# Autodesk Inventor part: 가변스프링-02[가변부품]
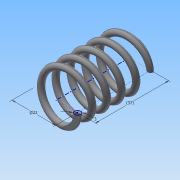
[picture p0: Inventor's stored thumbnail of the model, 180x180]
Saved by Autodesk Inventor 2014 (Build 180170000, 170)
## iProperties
Created: 2015-09
Part Number: 가변스프링-02[가변부품]
Material: 강철, 탄소
Document SubType Name: Modeling
Designer: study
Density: 7.87 g/cm^3
Appearance: 반연마
Mass: 18.8856 g
Surface Area: 32.5491 cm^2
Volume: 2.3997 cm^3
Author: study
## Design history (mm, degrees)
sketch "스케치1"
  geometry: L1 (0, 0)-(11, 0); L2 (11, 0)-(11, 36.411); L3 (11, 36.411)-(0, 36.411); L4 (0, 36.411)-(0, 0); C1 r 1.5 at (11, 0)
  constraints: 8 end point, 2 parallel, 1 centre point, 1 coincident, 1 horizontal, 1 perpendicular
  dimensions: "d0" = 22 diameter of L2 L4; "d1" = 36.4112 distance of L1.end L2.end (derived); "d2" = 3 diameter of C1
feature "코일1" sketch "스케치1" pitch "d3" = 10; turns "d5" = 5; dims "d4" = 36.4112 (= d1), "d6" = 0, angle "d7" = 90 deg, angle "d8" = 90 deg, "d9" = 0, "d10" = 0
sketch "스케치2"
  geometry: L1 (-12.5, 0)-(-9.5, 0) reference; L2 (-12.5, 0)-(-9.5, 0) reference; 1 further point
  constraints: 2 horizontal alignment
extrude "돌출1" cut sketch "스케치2" stored distance "d11" = 10; taper "d12" = 0 deg
node "작업 평면1"
sketch "스케치3"
  geometry: L1 (-9.5, 0)-(-12.5, 0) reference; 1 further point
  constraints: 1 horizontal alignment
extrude "돌출2" cut sketch "스케치3" stored distance "d14" = 10; taper "d15" = 0 deg
node "솔리드1"
node "절단 모서리 투영1"
node "절단 모서리 투영2"
node "절단 모서리 투영3"
other parameters: "d13" = 36.4112 (= d1)
